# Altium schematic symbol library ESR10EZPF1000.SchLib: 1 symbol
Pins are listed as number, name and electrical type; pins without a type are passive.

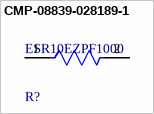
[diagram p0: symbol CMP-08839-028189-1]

## CMP-08839-028189-1
designator R?, comment ESR10EZPF1000
100Ω ±1% 0.4W 0805 Anti-Surge Chip Resistor AEC-Q200; Resistance: 100R; Max Power Dissipation: 400mW; Temperature Coefficient: 100ppm/°C
footprint FP-ESR10-IPC_C
footprint FP-ESR10-IPC_B
footprint FP-ESR10-IPC_A
footprint FP-ESR10-MFG
pins: 1, 2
